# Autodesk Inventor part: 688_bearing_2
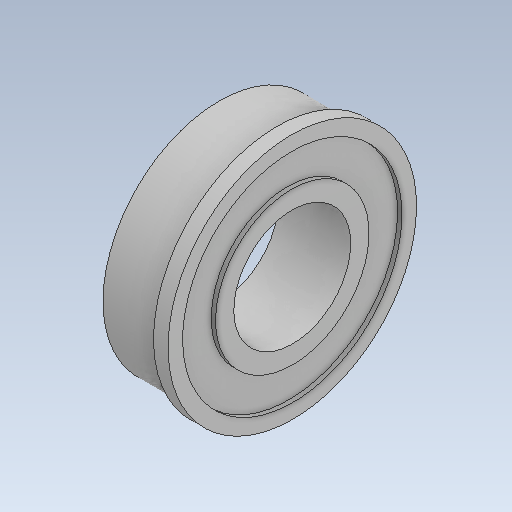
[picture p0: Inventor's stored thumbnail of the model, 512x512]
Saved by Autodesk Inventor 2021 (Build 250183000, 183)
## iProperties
Created: 2026-10
Part Number: 688_bearing_2
Material: Steel
Document SubType Name: Modeling
Designer: hp
Density: 7.85 g/cm^3
Appearance: Default
Author: hp
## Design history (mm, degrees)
feature "Body1"
body "Solid1"
